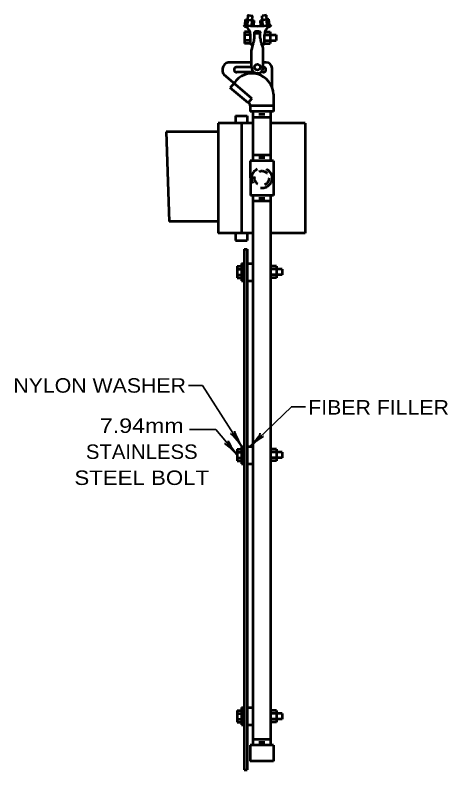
# Model space of a CAD drawing. Extents: x -35 to 821, y -10 to 534.
# Drawn here: x 256.9 to 346.7, y 232.5 to 389.1 of the extents above; entities that cross this region are included whole.
import ezdxf
from ezdxf.enums import TextEntityAlignment as Align

# ---------------------------------------------------------------- set-up
doc = ezdxf.new("R2010")
doc.units = 0
doc.header["$LTSCALE"] = 1.2
doc.linetypes.add('MEDIUM_DASHED', pattern=[4.5, 3, -1.5])
doc.linetypes.add('SHORT_DASHED', pattern=[2.7, 1.5, -1.2])
doc.layers.add('1', color=7, linetype='Continuous', lineweight=35)

msp = doc.modelspace()

# ---------------------------------------------------------------- linework, layer by layer
at = {"layer": '1', "lineweight": 53}
for p, q in [((306.023, 386.844), (306.166, 388.902)), ((309.593, 388.216), (307.809, 387.974)), ((309.066, 389.073), (308.196, 388.903)), ((308.34, 386.841), (308.196, 388.903)), ((309.254, 386.927), (309.066, 389.073)), ((309.7, 386.988), (309.593, 388.216)), ((304.669, 386.993), (304.751, 388.174)), ((304.751, 388.174), (306.552, 387.973)), ((306.472, 386.818), (306.552, 387.973)), ((307.89, 386.817), (307.809, 387.974)), ((305.648, 385.612), (304.537, 385.612)), ((304.537, 385.612), (304.537, 383.212)), ((306.603, 384.295), (306.603, 385.495)), ((307.803, 384.295), (307.803, 385.495)), ((308.758, 385.612), (309.868, 385.612)), ((309.868, 385.612), (309.868, 383.212)), ((305.737, 385.012), (304.537, 385.012)), ((305.737, 383.812), (304.537, 383.812)), ((305.737, 383.212), (305.737, 385.012)), ((308.668, 383.212), (308.668, 385.012)), ((308.668, 385.012), (311.068, 385.012)), ((308.668, 383.812), (311.068, 383.812)), ((311.068, 385.012), (311.068, 383.812)), ((305.737, 383.212), (304.537, 383.212)), ((308.668, 383.212), (309.868, 383.212)), ((306.003, 378.295), (306.003, 381.894)), ((308.403, 378.295), (308.403, 381.894)), ((306.003, 379.257), (301.625, 379.257)), ((309.026, 379.257), (308.403, 379.257)), ((306.003, 378.295), (302.953, 378.295)), ((310.226, 373.989), (310.226, 378.058)), ((306.042, 371.789), (300.3, 376.668)), ((306.536, 377.222), (302.953, 377.222)), ((308.403, 377.222), (307.87, 377.222)), ((302.343, 374.932), (301.566, 374.017)), ((305.265, 370.874), (301.566, 374.017)), ((310.526, 372.658), (310.526, 369.058)), ((306.042, 371.789), (305.265, 370.874)), ((302.672, 368.185), (302.672, 366.685)), ((302.672, 368.185), (305.072, 368.185)), ((305.072, 368.185), (305.072, 366.685)), ((310.526, 369.058), (305.672, 369.058)), ((306.272, 369.058), (306.272, 358.858)), ((309.926, 367.858), (306.272, 367.858)), ((308.726, 368.458), (307.472, 368.458)), ((309.926, 369.058), (309.926, 358.858)), ((306.272, 366.685), (299.072, 366.685)), ((303.872, 366.685), (303.872, 343.843)), ((317.126, 366.685), (309.926, 366.685)), ((317.126, 366.685), (317.126, 343.843)), ((299.072, 364.885), (288.272, 364.885)), ((288.272, 364.885), (288.872, 346.243)), ((309.926, 360.058), (306.272, 360.058)), ((310.526, 358.858), (305.728, 358.858)), ((305.728, 358.858), (305.732, 351.658)), ((308.726, 359.458), (307.472, 359.458)), ((310.526, 358.858), (310.526, 351.658)), ((310.526, 351.658), (305.732, 351.658)), ((308.726, 351.058), (307.472, 351.058)), ((309.926, 351.658), (309.926, 306.058)), ((309.926, 350.458), (306.272, 350.458)), ((299.072, 346.243), (288.872, 346.243)), ((306.272, 343.843), (299.072, 343.843)), ((302.672, 343.843), (302.672, 342.343)), ((305.072, 343.843), (305.072, 342.343)), ((317.126, 343.843), (309.926, 343.843)), ((302.672, 342.343), (305.072, 342.343)), ((304.472, 340.543), (304.472, 232.543)), ((304.472, 340.543), (305.072, 340.543)), ((305.072, 340.543), (305.072, 232.543)), ((302.972, 336.977), (303.872, 336.977)), ((302.972, 336.977), (302.972, 334.577)), ((303.872, 337.577), (303.872, 333.977)), ((303.872, 337.577), (304.472, 337.577)), ((305.072, 337.577), (306.272, 337.577)), ((311.133, 336.977), (309.933, 336.977)), ((311.133, 336.977), (311.133, 334.577)), ((302.972, 336.377), (303.872, 336.377)), ((302.972, 335.177), (303.872, 335.177)), ((312.333, 336.377), (309.933, 336.377)), ((312.333, 335.177), (309.933, 335.177)), ((312.333, 336.377), (312.333, 335.177)), ((302.972, 334.577), (303.872, 334.577)), ((303.872, 333.977), (304.472, 333.977)), ((305.072, 333.977), (306.272, 333.977)), ((311.133, 334.577), (309.933, 334.577)), ((309.926, 306.058), (309.926, 237.657)), ((302.972, 299.031), (303.872, 299.031)), ((302.972, 299.031), (302.972, 296.631)), ((303.872, 299.631), (303.872, 296.031)), ((303.872, 299.631), (304.472, 299.631)), ((305.072, 299.631), (306.272, 299.631)), ((311.133, 299.031), (309.933, 299.031)), ((311.133, 299.031), (311.133, 296.631)), ((302.972, 298.431), (303.872, 298.431)), ((312.333, 298.431), (309.933, 298.431)), ((312.333, 298.431), (312.333, 297.231)), ((302.972, 297.231), (303.872, 297.231)), ((302.972, 296.631), (303.872, 296.631)), ((303.872, 296.031), (304.472, 296.031)), ((305.072, 296.031), (306.272, 296.031)), ((312.333, 297.231), (309.933, 297.231)), ((311.133, 296.631), (309.933, 296.631)), ((302.972, 244.858), (303.872, 244.858)), ((302.972, 244.858), (302.972, 242.458)), ((302.972, 244.258), (303.872, 244.258)), ((303.872, 245.458), (303.872, 241.858)), ((303.872, 245.458), (304.472, 245.458)), ((305.072, 245.458), (306.272, 245.458)), ((311.133, 244.858), (309.933, 244.858)), ((312.333, 244.258), (309.933, 244.258)), ((311.133, 244.858), (311.133, 242.458)), ((312.333, 244.258), (312.333, 243.058)), ((302.972, 243.058), (303.872, 243.058)), ((312.333, 243.058), (309.933, 243.058)), ((302.972, 242.458), (303.872, 242.458)), ((303.872, 241.858), (304.472, 241.858)), ((305.072, 241.858), (306.272, 241.858)), ((311.133, 242.458), (309.933, 242.458)), ((309.926, 238.858), (306.272, 238.858)), ((308.726, 238.258), (307.472, 238.258)), ((305.672, 237.657), (305.672, 234.358)), ((310.526, 237.657), (305.672, 237.657)), ((310.526, 237.657), (310.526, 234.358)), ((310.526, 234.358), (305.672, 234.358)), ((304.472, 232.543), (305.072, 232.543))]:
    msp.add_line(p, q, dxfattribs=at)
at = {"layer": '1'}
for p, q in [((295.793, 312.237), (292.931, 312.254)), ((303.886, 299.631), (295.793, 312.237))]:
    msp.add_line(p, q, dxfattribs=at)
at = {"layer": '1', "lineweight": 53}
for points in [[(305.116, 386.932), (305.263, 389.04), (306.166, 388.902)], [(310.526, 370.257), (305.672, 370.257), (305.672, 369.058)], [(299.072, 366.685), (299.072, 364.885), (299.072, 346.243), (299.072, 343.843)], [(306.272, 351.658), (306.272, 306.058), (306.272, 237.657)]]:
    msp.add_lwpolyline(points, dxfattribs=at)
at = {"layer": '1'}
for points in [[(305.665, 299.631), (314.247, 307.845), (317.157, 307.845)], [(302.972, 297.851), (298.562, 303.135), (293.101, 303.135)]]:
    msp.add_lwpolyline(points, dxfattribs=at)
at = {"layer": '1', "lineweight": 53}
msp.add_circle((307.202, 378.285), 0.6, dxfattribs=at)
at = {"layer": '1', "linetype": 'MEDIUM_DASHED', "lineweight": 53}
msp.add_circle((308.107, 355.265), 2.1, dxfattribs=at)
at = {"layer": '1', "linetype": 'SHORT_DASHED', "lineweight": 53}
msp.add_circle((308.107, 355.265), 1.5, dxfattribs=at)
at = {"layer": '1', "lineweight": 53}
for centre, radius, start, end in [((305.04, 387.335), 0.733, 203.58004, 252.01356), ((307.203, 403.748), 16.945, 260.37064, 279.62936), ((303.905, 385.046), 1.833, 358.96049, 60.26465), ((310.501, 385.046), 1.833, 119.73535, 181.03951), ((309.365, 387.335), 0.733, 287.98644, 336.41996), ((299.2, 385.332), 7.475, 342.58659, 352.02537), ((310.426, 384.255), 2.623, 179.13382, 206.25421), ((306.061, 383.283), 0.331, 192.3337, 325.25389), ((308.745, 381.786), 2.744, 151.53189, 177.7435), ((308.35, 383.258), 0.322, 210.61838, 351.79404), ((305.661, 381.786), 2.744, 2.2565, 28.46811), ((301.472, 377.702), 1.563, 84.35792, 221.42863), ((309.026, 378.058), 1.2, 0, 90), ((302.914, 377.758), 0.538, 85.93331, 274.06669), ((307.203, 378.222), 1.202, 176.52918, 3.47082), ((308.441, 377.758), 0.538, 265.93331, 94.06669), ((306.08, 372.517), 4.449, 1.80469, 147.13236), ((305.265, 370.431), 0.443, 336.87776, 89.95193)]:
    msp.add_arc(centre, radius, start, end, dxfattribs=at)
msp.add_ellipse((307.203, 385.495), major_axis=(0.6, 0), ratio=0.434926, dxfattribs=at)
at = {"layer": '1', "lineweight": 40}
for centre, major_axis, ratio, start_param, end_param in [((302.899, 300.554), (1.315, -1.702), 0.122415, 0.8963533, 3.1415927), ((302.899, 300.554), (1.315, -1.702), 0.122415, 0.8963533, 3.1415927), ((303.373, 300.9), (-0.961, 1.888), 0.07063, 6.2823074, 8.5597026), ((303.373, 300.9), (-0.961, 1.888), 0.07063, 6.2823074, 8.5597026), ((306.382, 300.776), (-1.419, -1.617), 0.122415, 0.8963533, 3.1415927), ((306.382, 300.776), (-1.419, -1.617), 0.122415, 0.8963533, 3.1415927), ((302.306, 299.046), (-1.189, 1.753), 0.07063, 6.2823074, 8.5597026), ((306.812, 300.377), (-1.668, -1.305), 0.07063, 3.1407148, 5.41811), ((306.812, 300.377), (-1.668, -1.305), 0.07063, 3.1407148, 5.41811), ((301.879, 298.644), (1.517, -1.525), 0.122415, 0.8963533, 3.1415927)]:
    msp.add_ellipse(centre, major_axis=major_axis, ratio=ratio, start_param=start_param, end_param=end_param, dxfattribs=at)

# ---------------------------------------------------------------- texts
at = {"layer": '1', "width": 1.1}
for s, p in [('NYLON WASHER', (256.568, 310.773)), ('FIBER FILLER', (317.738, 306.231))]:
    msp.add_text(s, height=3, dxfattribs=at).set_placement(p)
at = {"layer": '1'}
for s, width, p in [('7.94mm', 1.2, (283.207, 302.431)), ('STAINLESS', 1.05, (283.207, 297.031)), ('STEEL BOLT', 1.15, (283.207, 291.631))]:
    msp.add_text(s, height=3, dxfattribs=dict(at, width=width)).set_placement(p, align=Align.CENTER)

doc.saveas('drawing.dxf')
